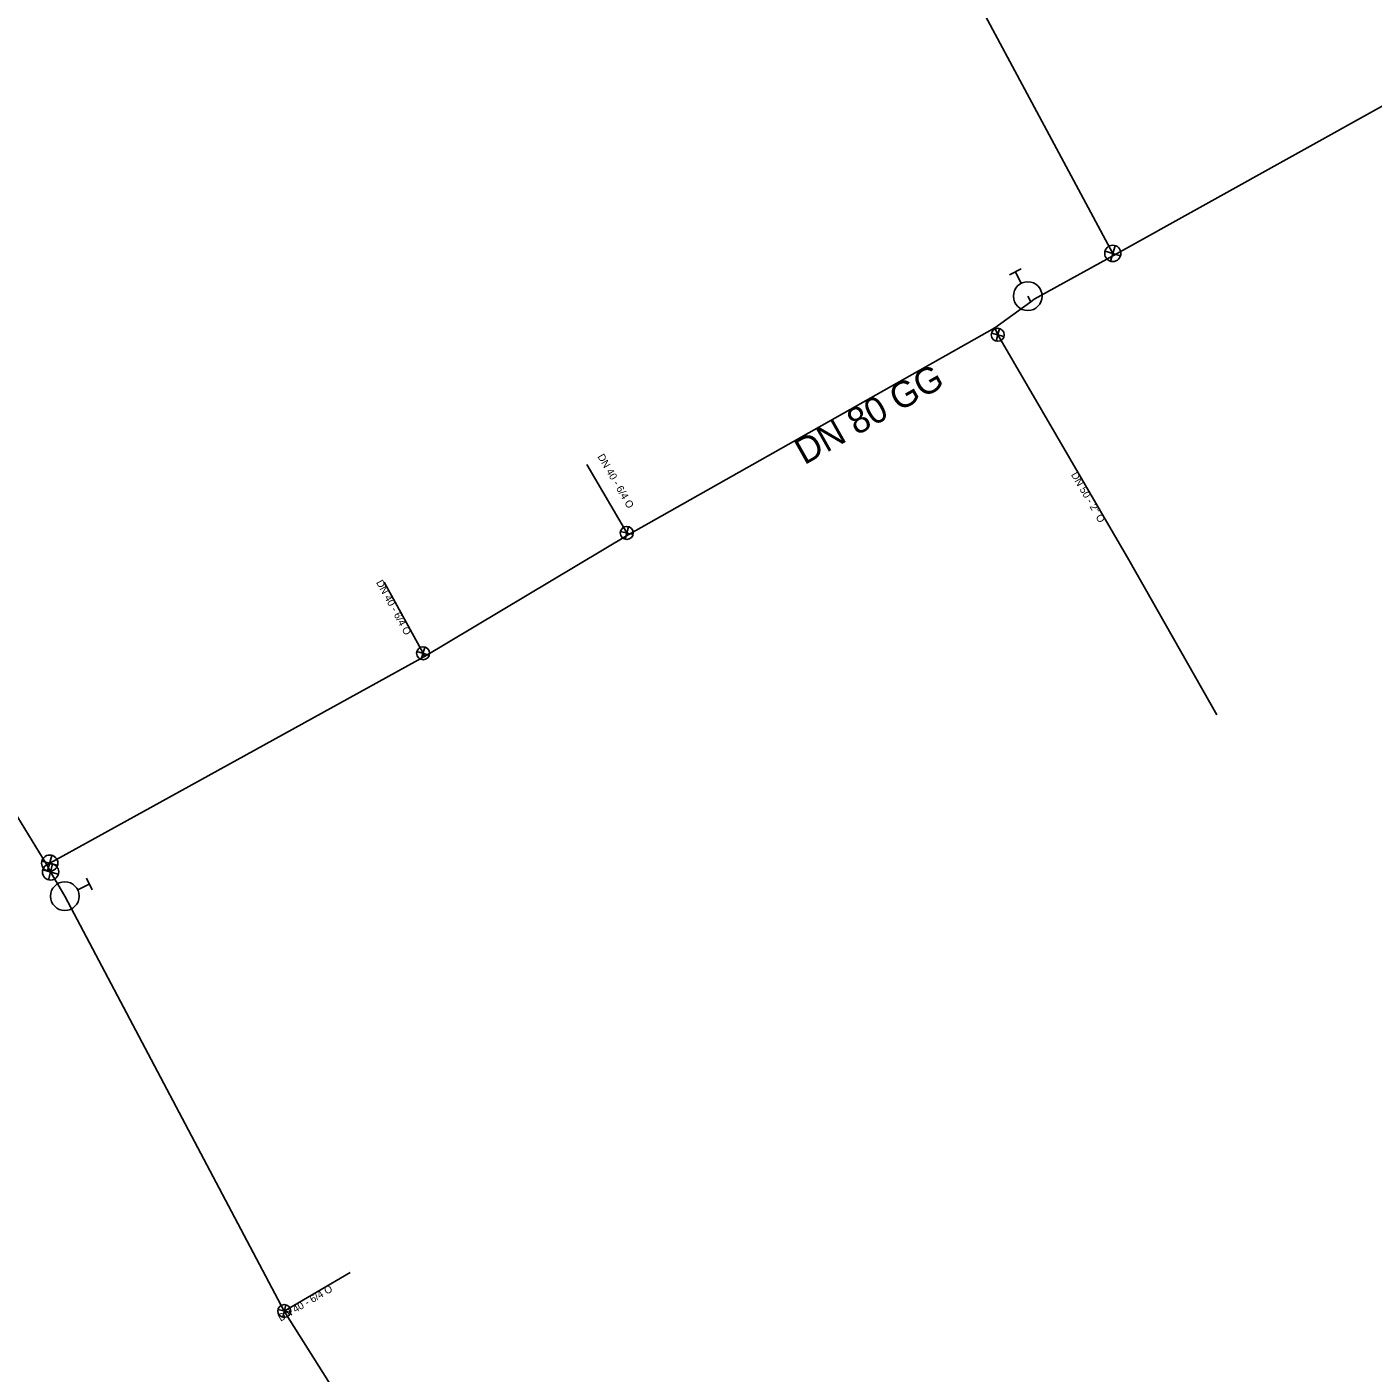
# Model space of a CAD drawing. Extents: x -443562 to -443270, y -1122830 to -1122511.
# Drawn here: x -443511 to -443428.1, y -1122675.2 to -1122592.4 of the extents above; entities that cross this region are included whole.
import ezdxf

# ---------------------------------------------------------------- set-up
doc = ezdxf.new("R2010")
doc.units = 0
for name, color, linetype in [('_hydrantova_odbocka_', 7, 'Continuous'), ('_pripojka_priblizne_', 7, 'Continuous'), ('_voda_smvak_prevzato_z_dokumentace_', 7, 'Continuous'), ('Default', 7, 'Continuous'), ('MoLevel 27', 7, 'Continuous'), ('MoLevel 28', 7, 'Continuous'), ('MoLevel 32', 7, 'Continuous'), ('MoLevel 46', 7, 'Continuous'), ('MoLevel 53', 7, 'Continuous')]:
    doc.layers.add(name, color=color, linetype=linetype)

# ---------------------------------------------------------------- blocks, each defined once
blk = doc.blocks.new('_uzaver_')
at = {"layer": 'Default'}
for p, q in [((-0.000035, -0.000035), (0.000035, 0.000035)), ((0.000035, -0.000035), (-0.000035, 0.000035))]:
    blk.add_line(p, q, dxfattribs=at)
for radius in [0.00005, 0.0000025]:
    blk.add_circle((0, 0), radius, dxfattribs=at)
blk = doc.blocks.new('_uzaver_pripojka_')
at = {"layer": 'Default'}
for p, q in [((-0.000035, -0.000035), (0.000035, 0.000035)), ((0.000035, -0.000035), (-0.000035, 0.000035))]:
    blk.add_line(p, q, dxfattribs=at)
for radius in [0.00005, 0.0000025]:
    blk.add_circle((0, 0), radius, dxfattribs=at)
blk = doc.blocks.new('_hydrant_voda_')
at = {"layer": 'Default'}
for p, q in [((-0.0000225, 0.000095), (0.0000225, 0.000095)), ((0, 0.000095), (0, 0.00005))]:
    blk.add_line(p, q, dxfattribs=at)
blk.add_circle((0, 0), 0.00005, dxfattribs=at)

msp = doc.modelspace()

# ---------------------------------------------------------------- linework, layer by layer
at = {"layer": '_hydrantova_odbocka_'}
msp.add_line((-443449.39, -1122608.97), (-443449.228, -1122609.279), dxfattribs=at)
at = {"layer": '_pripojka_priblizne_'}
for p, q in [((-443443.165, -1122625.191), (-443437.751, -1122634.73)), ((-443495.13, -1122671.4), (-443491.08, -1122669.03))]:
    msp.add_line(p, q, dxfattribs=at)
for points in [[(-443451.412, -1122610.92), (-443451.24, -1122611.35), (-443443.165, -1122625.191)], [(-443473.98, -1122623.66), (-443474.06, -1122623.54), (-443476.513, -1122619.332)], [(-443486.5, -1122631.13), (-443486.59, -1122630.94), (-443488.989, -1122626.559)]]:
    msp.add_lwpolyline(points, dxfattribs=at)
at = {"layer": '_voda_smvak_prevzato_z_dokumentace_'}
for p, q in [((-443444.16, -1122606.34), (-443444.123, -1122606.462)), ((-443511.998, -1122640.261), (-443509.735, -1122643.963)), ((-443509.735, -1122643.963), (-443509.56, -1122643.85)), ((-443509.735, -1122643.963), (-443509.51, -1122644.39)), ((-443509.51, -1122644.39), (-443508.63, -1122645.88))]:
    msp.add_line(p, q, dxfattribs=at)
for points in [[(-443454.43, -1122511.082), (-443446.83, -1122524.61), (-443437.55, -1122540.82), (-443426.745, -1122560.078), (-443428.435, -1122566.587), (-443446.09, -1122575.63), (-443457.423, -1122581.604), (-443444.16, -1122606.34)], [(-443444.123, -1122606.462), (-443421.765, -1122594.051), (-443406.516, -1122620.09), (-443396.35, -1122636.96), (-443385.877, -1122655.347), (-443384.03, -1122658.96)], [(-443449.197, -1122609.314), (-443449.006, -1122609.149), (-443444.123, -1122606.462)], [(-443509.56, -1122643.85), (-443486.5, -1122631.13), (-443473.98, -1122623.66), (-443451.412, -1122610.92), (-443449.197, -1122609.314)], [(-443508.63, -1122645.88), (-443495.13, -1122671.4), (-443484.93, -1122687.61), (-443476.13, -1122703.74), (-443467.08, -1122719.85), (-443457.463, -1122735.742), (-443449.31, -1122750.61), (-443442.813, -1122761.691)]]:
    msp.add_lwpolyline(points, dxfattribs=at)

# ---------------------------------------------------------------- block references
at = {"layer": 'MoLevel 27'}
for p, xscale, yscale, rotation in [((-443444.16, -1122606.34), 10000, 10000.000000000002, 118.09772546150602), ((-443509.56, -1122643.85), 9999.999999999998, 10000.000000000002, 29.6659861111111), ((-443509.51, -1122644.39), 10000, 10000, -60.048810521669)]:
    msp.add_blockref('_uzaver_', p, dxfattribs=dict(at, xscale=xscale, yscale=yscale, rotation=rotation))
at = {"layer": 'MoLevel 28'}
for p, xscale, yscale, rotation in [((-443449.39, -1122608.97), 17636.68430335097, 17636.684303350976, 27.124930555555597), ((-443508.63, -1122645.88), 17636.684303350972, 17636.68430335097, -63.762116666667)]:
    msp.add_blockref('_hydrant_voda_', p, dxfattribs=dict(at, xscale=xscale, yscale=yscale, rotation=rotation))
at = {"layer": 'MoLevel 53', "xscale": 8000}
for p, yscale, rotation in [((-443451.24, -1122611.35), 7999.999999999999, -59.74108654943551), ((-443474.06, -1122623.54), 8000, 120.239637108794), ((-443486.59, -1122630.94), 7999.999999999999, 118.12727609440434), ((-443495.13, -1122671.4), 7999.999999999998, 30.335538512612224)]:
    msp.add_blockref('_uzaver_pripojka_', p, dxfattribs=dict(at, yscale=yscale, rotation=rotation))

# ---------------------------------------------------------------- texts
at = {"layer": 'MoLevel 32'}
for s, rotation, p in [('DN 40 - 6/4 O', 300.23964, (-443475.878, -1122618.836)), ("DN 50 - 2'' O", 300.25892, (-443446.748, -1122619.953)), ('DN 40 - 6/4 O', 298.70886, (-443489.496, -1122626.581)), ('DN 40 - 6/4 O', 30.33554, (-443495.353, -1122672.058))]:
    msp.add_text(s, height=0.455, rotation=rotation, dxfattribs=at).set_placement(p)
at = {"layer": 'MoLevel 46'}
msp.add_text('DN 80 GG', height=1.6049, rotation=29.44656, dxfattribs=at).set_placement((-443463.134, -1122619.38))

doc.saveas('drawing.dxf')
